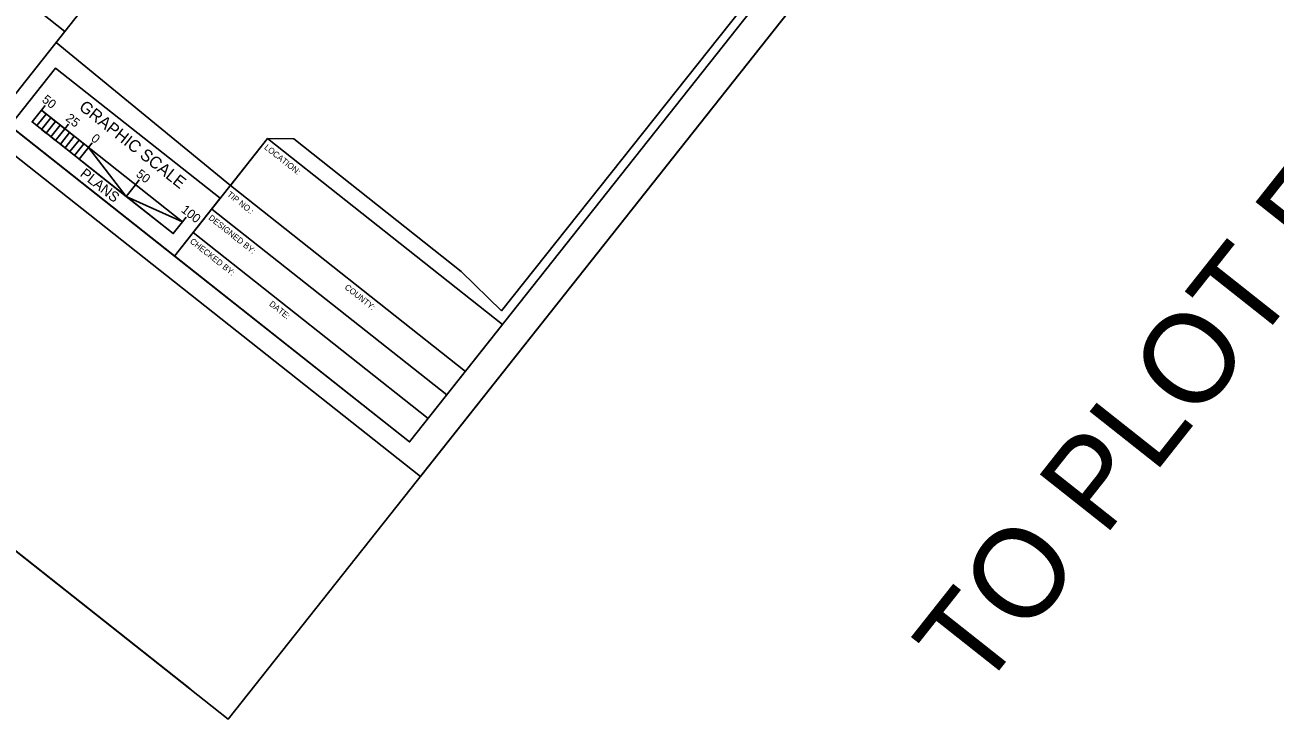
# Model space of a CAD drawing. Extents: x 1771636 to 1784627, y 798645 to 819978.
# Drawn here: x 1782923 to 1783965, y 810983 to 811562 of the extents above; entities that cross this region are included whole.
import ezdxf

# ---------------------------------------------------------------- set-up
doc = ezdxf.new("R2010")
doc.units = 0
for name, color, linetype in [('CTL North Arrow CELL', 7, 'Continuous'), ('Exist Hydro Stream Flow Arrow CELL', 7, 'Continuous'), ('Exist Other Culture Well CELL', 7, 'Continuous'), ('Exist Structure Minor Footbridge Terminator', 7, 'Continuous'), ('Exist Utilities Power Joint Use Telephone CELL', 7, 'Continuous'), ('Exist Utilities Telephone Pole CELL', 7, 'Continuous')]:
    doc.layers.add(name, color=color, linetype=linetype)

msp = doc.modelspace()

# ---------------------------------------------------------------- linework, layer by layer
at = {"layer": 'CTL North Arrow CELL'}
msp.add_line((1780451.8, 813073.9), (1783060.5, 811008.6), dxfattribs=at)
at = {"layer": 'Exist Hydro Stream Flow Arrow CELL'}
msp.add_lwpolyline([(1784297.9, 812505.9), (1781710.6, 814554.3), (1780665.3, 813234), (1783252.6, 811185.6)], close=True, dxfattribs=at)
at = {"layer": 'Exist Other Culture Well CELL'}
msp.add_lwpolyline([(1784458, 812708.2), (1781817.4, 814798.8), (1780451.8, 813073.9), (1783092.4, 810983.3)], close=True, dxfattribs=at)
at = {"layer": 'Exist Structure Minor Footbridge Terminator'}
msp.add_lwpolyline([(1782581.1, 811750.2), (1782905.6, 811493.3), (1782969.7, 811574.2), (1782645.2, 811831.2)], close=True, dxfattribs=at)
at = {"layer": 'Exist Utilities Power Joint Use Telephone CELL'}
for p, q in [((1782936.5, 811491.2), (1782928.8, 811481.5)), ((1782936.5, 811491.2), (1782939.6, 811495.1)), ((1783054.1, 811398.1), (1782936.5, 811491.2)), ((1782940.2, 811495.9), (1782940.2, 811495.9)), ((1782928.8, 811481.5), (1783046.4, 811388.4)), ((1782944.3, 811485), (1782936.6, 811475.3)), ((1782956.1, 811475.7), (1782959.2, 811479.6)), ((1782959.8, 811480.4), (1782959.8, 811480.4)), ((1782975.7, 811460.2), (1782978.8, 811464.1)), ((1783018.5, 811433.9), (1783018.5, 811433.9)), ((1783014.9, 811429.1), (1783007.2, 811419.4)), ((1783007.2, 811419.4), (1783014.9, 811429.1)), ((1783014.9, 811429.1), (1783018, 811433.1)), ((1783094.1, 811428.4), (1783290.1, 811273.3)), ((1783058.1, 811402.6), (1783058.1, 811402.6)), ((1783078.6, 811408.8), (1783274.6, 811253.7)), ((1783054.1, 811398.1), (1783057.2, 811402)), ((1783063, 811389.2), (1783259, 811234.1))]:
    msp.add_line(p, q, dxfattribs=at)
for points in [[(1781915.6, 814370.3), (1784267.7, 812508.1), (1783243.5, 811214.5), (1780891.4, 813076.6)], [(1782910.3, 811478.3), (1783047.5, 811369.6), (1783085.6, 811417.8), (1782948.4, 811526.4)], [(1782936.5, 811491.2), (1782940.4, 811488.1), (1782932.7, 811478.4), (1782928.8, 811481.5)], [(1782944.3, 811485), (1782948.3, 811481.9), (1782940.6, 811472.2), (1782936.6, 811475.3)], [(1782952.2, 811478.8), (1782956.1, 811475.7), (1782948.4, 811466), (1782944.5, 811469.1)], [(1782960, 811472.6), (1782963.9, 811469.5), (1782956.2, 811459.8), (1782952.3, 811462.9)], [(1782967.9, 811466.4), (1782971.8, 811463.3), (1782964.1, 811453.6), (1782960.2, 811456.7)], [(1783047.5, 811369.6), (1783243.5, 811214.5), (1783321.1, 811312.5), (1783125.1, 811467.6)], [(1782975.7, 811460.2), (1783007.2, 811419.4), (1782968, 811450.4)], [(1783054.1, 811398.1), (1783007.2, 811419.4), (1783046.4, 811388.4)]]:
    msp.add_lwpolyline(points, close=True, dxfattribs=at)
at = {"layer": 'Exist Utilities Telephone Pole CELL'}
msp.add_lwpolyline([(1783384.7, 813185.4), (1782922.7, 812601.8), (1782968.4, 812565.5), (1783541, 812112.3), (1783700.5, 812313.7), (1783949.3, 812116.7), (1783784.1, 811908), (1783320.2, 811324), (1783286.6, 811356.7), (1783146.9, 811467.3), (1783125.1, 811467.6), (1783094.1, 811428.4), (1782948.7, 811547.7), (1782956.1, 811557), (1782756.8, 811714.8), (1782728.2, 811696), (1782447, 811920.2), (1782412.5, 811881.5), (1782072.9, 812146.5), (1782110.3, 812188.5), (1781507.5, 812669.1)], dxfattribs=at)

# ---------------------------------------------------------------- texts
at = {"layer": 'Exist Utilities Power Joint Use Telephone CELL'}
for s, height, rotation, p in [('TO PLOT FULL SIZE 62"X34"', 75, 51.6309, (1783719.1, 811003.4)), ('50', 7.5, 321.6309, (1782936.4, 811498.9)), ('GRAPHIC SCALE', 10, 321.6309, (1782967.1, 811492.5)), ('25', 7.5, 321.6309, (1782956.1, 811483.4)), ('0', 7.5, 321.6309, (1782977.3, 811466.5)), ('LOCATION:', 5, 321.6309, (1783121.9, 811459.4)), ('PLANS', 8.5, 321.6309, (1782968.1, 811436.9)), ('50', 7.5, 321.6309, (1783014.9, 811436.8)), ('TIP NO.:', 5, 321.6309, (1783090.9, 811420.2)), ('100', 7.5, 321.6309, (1783052.5, 811407)), ('DESIGNED BY:', 5, 321.6309, (1783075.4, 811400.6)), ('CHECKED BY:', 5, 321.6309, (1783059.9, 811381)), ('COUNTY:', 5, 321.6309, (1783188.9, 811342.7)), ('DATE:', 5, 321.6309, (1783126, 811328.7))]:
    msp.add_text(s, height=height, rotation=rotation, dxfattribs=at).set_placement(p)

doc.saveas('drawing.dxf')
